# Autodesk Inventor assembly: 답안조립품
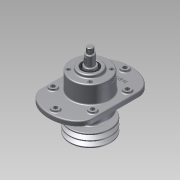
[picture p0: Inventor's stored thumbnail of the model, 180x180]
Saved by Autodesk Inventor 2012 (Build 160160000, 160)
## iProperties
Created: 2015-02
Part Number: 답안조립품
Document SubType Name: Assembly
Designer: Administrator
Author: Administrator
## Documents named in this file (11)
- C:\Documents and Settings\Administrator\바탕 화면\450207V1003\답안조립품.iam
- C:\Documents and Settings\Administrator\바탕 화면\450207V1003\1-본체.ipt
- C:\Documents and Settings\Administrator\바탕 화면\450207V1003\6-베어링 6206.ipt
- C:\Documents and Settings\Administrator\바탕 화면\450207V1003\7-부시.ipt
- C:\Documents and Settings\Administrator\바탕 화면\450207V1003\3-축.ipt
- C:\Documents and Settings\Administrator\바탕 화면\450207V1003\2-커버.ipt
- C:\Documents and Settings\Administrator\바탕 화면\450207V1003\11-키 6x6.ipt
- C:\Documents and Settings\Administrator\바탕 화면\450207V1003\8-오일실 30x42.ipt
- C:\Documents and Settings\Administrator\바탕 화면\450207V1003\10-M6.ipt
- C:\Documents and Settings\Administrator\바탕 화면\450207V1003\4-V벨트풀리.ipt
- C:\Documents and Settings\Administrator\바탕 화면\450207V1003\9-M16-너트.ipt
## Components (21 placed, 10 different names)
1. 1-본체:1
2. 6-베어링 6206:1
3. 7-부시:1
4. 3-축:1
5. 6-베어링 6206:2
6. 2-커버:1
7. 2-커버:2
8. 11-키 6x6:1
9. 11-키 6x6:2
10. 8-8-오일실 30x42:1
11. 8-8-오일실 30x42:2
12. 10-M6:1
13. 10-M6:2
14. 10-M6:3
15. 10-M6:4
16. 10-M6:5
17. 10-M6:6
18. 10-M6:7
19. 10-M6:8
20. 4-V벨트풀리:1
21. 9-M16 너트:1
